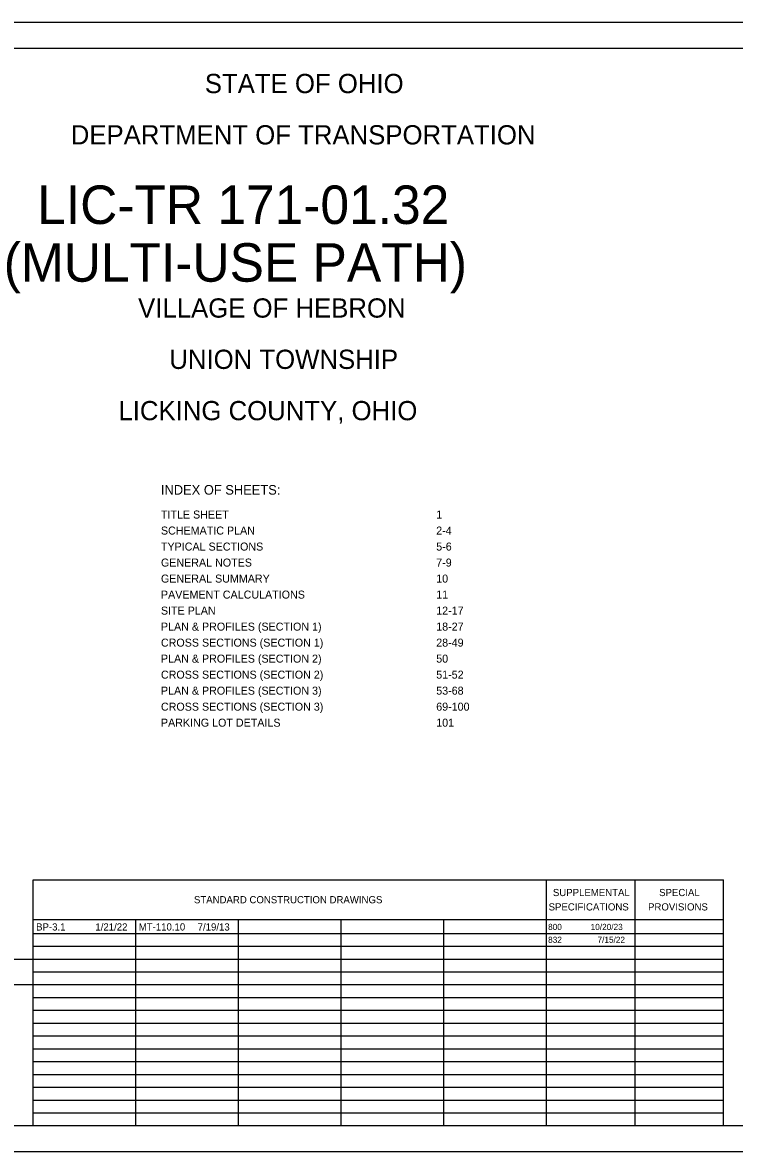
# Model space of a CAD drawing. Extents: x 0 to 40.4, y 0 to 22.
# Drawn here: x 11.84 to 25.71, y 0 to 22 of the extents above; entities that cross this region are included whole.
import ezdxf

# ---------------------------------------------------------------- set-up
doc = ezdxf.new("R2010")
doc.units = 0
for name, color, linetype in [('SH_Border', 7, 'Continuous'), ('SH_Cut_Line', 7, 'Continuous'), ('SH_Data', 7, 'Continuous')]:
    doc.layers.add(name, color=color, linetype=linetype)

msp = doc.modelspace()

# ---------------------------------------------------------------- linework, layer by layer
at = {"layer": 'SH_Border'}
msp.add_lwpolyline([(2, 21.5), (33.5, 21.5), (33.5, 0.5), (2, 0.5)], close=True, dxfattribs=at)
at = {"layer": 'SH_Cut_Line'}
msp.add_lwpolyline([(0, 0), (34, 0), (34, 22), (0, 22)], close=True, dxfattribs=at)
at = {"layer": 'SH_Data'}
for p, q in [((12.05, 5.292), (25.5, 5.292)), ((12.05, 0.5), (12.05, 5.292)), ((22.05, 0.5), (22.05, 5.292)), ((23.775, 0.5), (23.775, 5.292)), ((25.5, 0.5), (25.5, 5.292)), ((12.05, 4.521), (25.5, 4.521)), ((14.05, 0.5), (14.05, 4.521)), ((16.05, 0.5), (16.05, 4.521)), ((18.05, 0.5), (18.05, 4.521)), ((20.05, 0.5), (20.05, 4.521)), ((12.05, 4.25), (22.05, 4.25)), ((22.05, 4.25), (25.5, 4.25)), ((12.05, 4), (25.5, 4)), ((9.25, 3.75), (12.05, 3.75)), ((12.05, 3.75), (25.5, 3.75)), ((12.05, 3.5), (25.5, 3.5)), ((9.25, 3.25), (12.05, 3.25)), ((12.05, 3.25), (25.5, 3.25)), ((12.05, 3), (25.5, 3)), ((12.05, 2.75), (25.5, 2.75)), ((12.05, 2.5), (25.5, 2.5)), ((12.05, 2.25), (25.5, 2.25)), ((12.05, 2), (25.5, 2)), ((12.05, 1.75), (25.5, 1.75)), ((12.05, 1.5), (25.5, 1.5)), ((12.05, 1.25), (25.5, 1.25)), ((12.05, 1), (25.5, 1)), ((12.05, 0.75), (25.5, 0.75))]:
    msp.add_line(p, q, dxfattribs=at)

# ---------------------------------------------------------------- texts
for s, height, p in [('STATE OF OHIO', 0.375, (15.392, 20.625)), ('DEPARTMENT OF TRANSPORTATION', 0.375, (12.78, 19.625)), ('LIC-TR 171-01.32', 0.75, (12.127, 18.075)), ('(MULTI-USE PATH)', 0.75, (11.474, 16.95)), ('VILLAGE OF HEBRON', 0.375, (14.092, 16.25)), ('UNION TOWNSHIP', 0.375, (14.7, 15.25)), ('LICKING COUNTY, OHIO', 0.375, (13.709, 14.25)), ('INDEX OF SHEETS:', 0.1875, (14.537, 12.8)), ('TITLE SHEET', 0.15597, (14.537, 12.334)), ('1', 0.156, (19.9, 12.334)), ('SCHEMATIC PLAN', 0.15597, (14.537, 12.022)), ('2-4', 0.156, (19.9, 12.022)), ('TYPICAL SECTIONS', 0.15597, (14.537, 11.71)), ('5-6', 0.156, (19.9, 11.71)), ('GENERAL NOTES', 0.15597, (14.537, 11.398)), ('7-9', 0.156, (19.9, 11.398)), ('GENERAL SUMMARY', 0.15597, (14.537, 11.086)), ('10', 0.156, (19.9, 11.086)), ('PAVEMENT CALCULATIONS', 0.15597, (14.537, 10.774)), ('11', 0.156, (19.9, 10.774)), ('SITE PLAN', 0.156, (14.537, 10.462)), ('12-17', 0.156, (19.9, 10.462)), ('PLAN & PROFILES (SECTION 1)', 0.15597, (14.537, 10.15)), ('18-27', 0.156, (19.9, 10.15)), ('CROSS SECTIONS (SECTION 1)', 0.15597, (14.537, 9.838)), ('28-49', 0.156, (19.9, 9.838)), ('PLAN & PROFILES (SECTION 2)', 0.15597, (14.537, 9.526)), ('50', 0.156, (19.9, 9.526)), ('CROSS SECTIONS (SECTION 2)', 0.15597, (14.537, 9.214)), ('51-52', 0.156, (19.9, 9.214)), ('PLAN & PROFILES (SECTION 3)', 0.15597, (14.537, 8.902)), ('53-68', 0.156, (19.9, 8.902)), ('CROSS SECTIONS (SECTION 3)', 0.15597, (14.537, 8.59)), ('69-100', 0.156, (19.9, 8.59)), ('PARKING LOT DETAILS', 0.15597, (14.537, 8.278)), ('101', 0.156, (19.9, 8.278)), ('SUPPLEMENTAL', 0.14, (22.173, 4.976)), ('SPECIAL', 0.14, (24.243, 4.976)), ('STANDARD CONSTRUCTION DRAWINGS', 0.14, (15.18, 4.836)), ('SPECIFICATIONS', 0.14, (22.09, 4.696)), ('PROVISIONS', 0.14, (24.027, 4.696)), ('BP-3.1', 0.14, (12.105, 4.305)), ('1/21/22', 0.14, (13.26, 4.305)), ('MT-110.10', 0.14, (14.105, 4.305)), ('7/19/13', 0.14, (15.252, 4.305)), ('800', 0.12, (22.08, 4.315)), ('10/20/23', 0.12, (22.909, 4.315)), ('832', 0.12, (22.08, 4.065)), ('7/15/22', 0.12, (23.043, 4.065))]:
    msp.add_text(s, height=height, dxfattribs=at).set_placement(p)

doc.saveas('drawing.dxf')
